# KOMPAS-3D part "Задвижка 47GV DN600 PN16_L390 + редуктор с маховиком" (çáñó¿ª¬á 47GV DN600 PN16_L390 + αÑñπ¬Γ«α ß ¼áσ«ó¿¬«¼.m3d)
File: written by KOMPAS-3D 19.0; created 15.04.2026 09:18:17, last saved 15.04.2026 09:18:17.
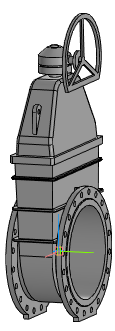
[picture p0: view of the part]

Document properties: Автор: Энергия; Полное имя файла: ..\..\Задвижка 47GV DN600 PN16_L390 + редуктор с маховиком.a3d

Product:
- Part/product: Задвижка 47GV DN600 PN16_L390 + редуктор с маховиком
    Масса: 1544.66

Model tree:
1. Операция без истории:1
